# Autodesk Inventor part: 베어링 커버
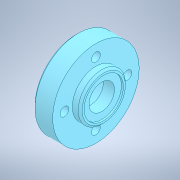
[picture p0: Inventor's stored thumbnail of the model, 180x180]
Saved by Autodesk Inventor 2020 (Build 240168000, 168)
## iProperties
Created: 2024-05
Part Number: 베어링 커버
Material: 강철, 연강
Document SubType Name: Modeling
Designer: oem
Density: 7.85 g/cm^3
Appearance: 기본값
Author: jhkim
Sending System: Autodesk Inventor 2025
Preprocessor: ST-DEVELOPER v20
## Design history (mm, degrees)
feature "솔리드1"
node "솔리드2"
